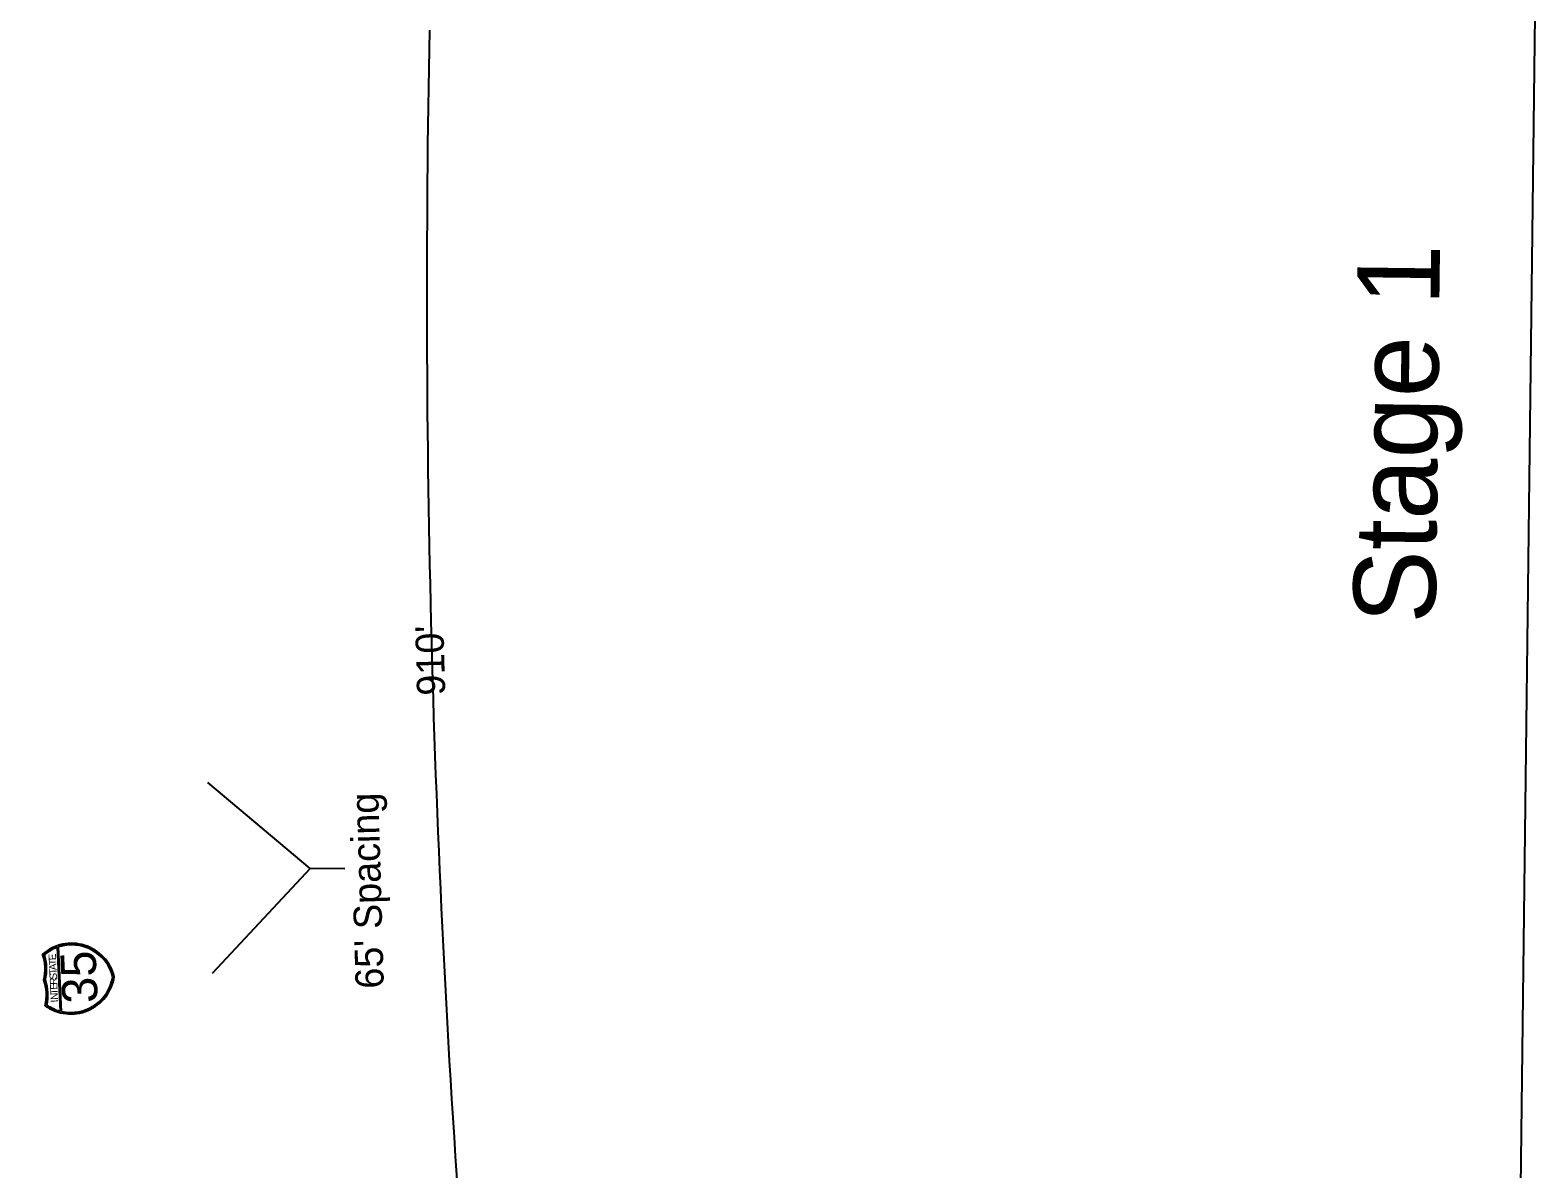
# Model space of a CAD drawing. Extents: x 4959127 to 4960275, y 3872379 to 3884458.
# Drawn here: x 4959633 to 4960146, y 3873480 to 3873867 of the extents above; entities that cross this region are included whole.
import ezdxf

# ---------------------------------------------------------------- set-up
doc = ezdxf.new("R2010")
doc.units = 0
for name, color, linetype in [('dsnCellsHighwaySymbols', 7, 'Continuous'), ('NamedBoundary', 7, 'Continuous'), ('SheetText', 7, 'Continuous'), ('Text', 7, 'Continuous')]:
    doc.layers.add(name, color=color, linetype=linetype)

msp = doc.modelspace()

# ---------------------------------------------------------------- linework, layer by layer
at = {"layer": 'dsnCellsHighwaySymbols'}
for p, q in [((4959642.25, 3873555.14), (4959643.27, 3873533.47)), ((4959643.78, 3873533.35), (4959642.74, 3873555.31))]:
    msp.add_line(p, q, dxfattribs=at)
for centre, radius, start, end in [((4959647.2, 3873541.51), 15, 14.2386, 131.0326), ((4959647.2, 3873541.51), 14.5, 109.9647, 129.7056), ((4959647.21, 3873541.51), 14.5, 14.6311, 107.9481), ((4959623.23, 3873547.77), 15, 345.7105, 19.6926), ((4959623.22, 3873547.81), 15.5, 346.127, 18.2625), ((4959623.65, 3873539.01), 15, 345.7105, 19.6926), ((4959646.92, 3873547.5), 15, 234.3704, 351.1644), ((4959623.64, 3873538.97), 15.5, 347.1406, 19.276), ((4959646.93, 3873547.5), 14.5, 257.4549, 350.772), ((4959646.92, 3873547.5), 14.5, 235.6974, 255.4381)]:
    msp.add_arc(centre, radius, start, end, dxfattribs=at)
at = {"layer": 'NamedBoundary'}
msp.add_lwpolyline([(4959126.87, 3872391.44), (4960126.8, 3872379.18), (4960146.01, 3873946.56), (4959146.09, 3873958.82)], close=True, dxfattribs=at)
at = {"layer": 'SheetText'}
msp.add_line((4959728.42, 3873582), (4959693.58, 3873611.26), dxfattribs=at)
msp.add_lwpolyline([(4959740.19, 3873581.86), (4959728.42, 3873582), (4959695.04, 3873546.25)], dxfattribs=at)
msp.add_arc((4964204.08, 3873777.26), 4436.04, 178.83867, 184.20824, dxfattribs=at)

# ---------------------------------------------------------------- texts
at = {"layer": 'dsnCellsHighwaySymbols'}
for s, height, p in [('E', 2.5, (4959641.95, 3873550.83)), ('T', 2.5, (4959642.03, 3873549.16)), ('A', 2.5, (4959642.11, 3873547.45)), ('35', 12, (4959656.15, 3873536.4)), ('T', 2.5, (4959642.18, 3873546.06)), ('S', 2.5, (4959642.26, 3873544.28)), ('R', 2.5, (4959642.35, 3873542.49)), ('E', 2.5, (4959642.43, 3873540.82)), ('T', 2.5, (4959642.51, 3873539.15)), ('N', 2.5, (4959642.59, 3873537.36)), ('I', 2.5, (4959642.63, 3873536.48))]:
    msp.add_text(s, height=height, rotation=92.7015, dxfattribs=at).set_placement(p)
at = {"layer": 'SheetText'}
for s, p in [("910'", (4959774.34, 3873640.95)), ("65' Spacing", (4959753.44, 3873541.21))]:
    msp.add_text(s, height=9.6, rotation=91.5955, dxfattribs=at).set_placement(p)
at = {"layer": 'Text'}
msp.add_text('Stage 1', height=28, rotation=89.2975, dxfattribs=at).set_placement((4960111.17, 3873665.17))

doc.saveas('drawing.dxf')
